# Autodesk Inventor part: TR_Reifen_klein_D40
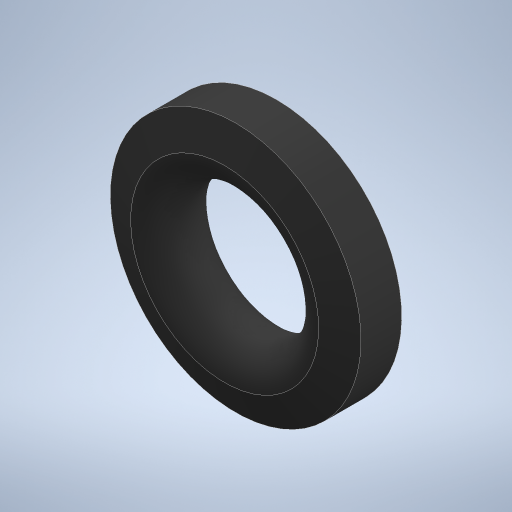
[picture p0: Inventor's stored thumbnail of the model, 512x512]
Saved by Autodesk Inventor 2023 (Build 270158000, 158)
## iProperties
Created: 2023-11
Part Number: TR_Reifen_klein_D40
Material: Gummi
Document SubType Name: Modeling
Designer: Administrator
Density: 0.93 g/cm^3
Appearance: Gummi - Schwarz
Author: Administrator
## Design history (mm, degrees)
sketch "Skizze1"
  geometry: L1 (15, 5)-(20, 3.25); L2 (20, 3.25)-(20, -3.25); L3 (20, -3.25)-(15, -5); L4 (0, -7)-(0, 7) reference; L5 (15, 5)-(26.75, 5); A1 r 5 centre (15, 0) between (15, 5) and (15, -5); 2 further points
  constraints: 8 end point, 2 horizontal alignment, 2 point on circle, 1 centre point, 1 horizontal, 1 midpoint, 1 tangent, 1 vertical, 1 vertical alignment
  dimensions: "d0" = 6.5 distance of L1.end L2.end; "d1" = 10 distance of L3.end L1.start; "d2" = 20 horizontal distance of point (0, 0) L1.end; "d3" = 5 horizontal distance of L3.end L2.end
revolve "Umdrehung1" sketch "Skizze1" stored, may be unused: angle "d4" = 90 deg
node "Volumenkörper1"
